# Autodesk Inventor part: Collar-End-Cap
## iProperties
Shininess: 64.0
Length Units: 11269
Angle Units: 11279
Time Units: 11290
Mass Units: 11283
Length Display Precision: 3
Angle Display Precision: 2
Compacted: True
Part Number: Collar-End-Cap
Document SubType Name: Modeling
Created: 2004-01
Designer: Administrator
Manufacturer: Standard
Standards Organization: Custom
Density: 1 g/cm^3
Density: 0.0
Volumn: 0.0
Area: 0.0
PropertySet Name: Model Information
Control State: 0
Master: False
Checked Out: False
Author: Administrator
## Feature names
1. Extrusion1
2. Hole1
3. Extrusion2
4. Chamfer1
